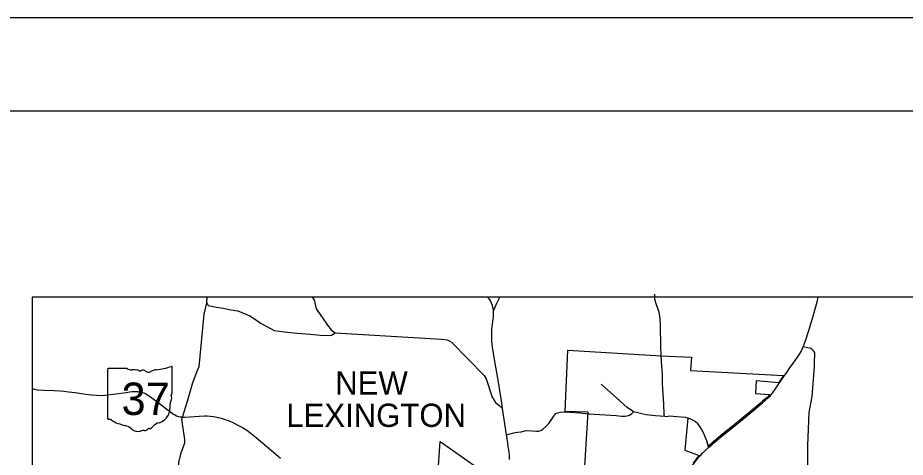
# Model space of a CAD drawing. Extents: x 2025369 to 2161369, y 549489 to 637489.
# Drawn here: x 2037061 to 2056140, y 628050 to 637489 of the extents above; entities that cross this region are included whole.
import ezdxf

# ---------------------------------------------------------------- set-up
doc = ezdxf.new("R2010")
doc.units = 0
for name, color, linetype in [('GM_X_City_Street', 7, 'Continuous'), ('GM_X_Corporation', 7, 'Continuous'), ('GM_X_Corporation_Text', 7, 'Continuous'), ('GM_X_County_Road', 7, 'Continuous'), ('GM_X_State_Route', 7, 'Continuous'), ('GM_X_State_Shield', 7, 'Continuous'), ('GM_X_Township_Road', 7, 'Continuous'), ('SH_Border', 7, 'Continuous'), ('SH_Cut_Line', 7, 'Continuous'), ('SH_Text', 7, 'Continuous')]:
    doc.layers.add(name, color=color, linetype=linetype)

msp = doc.modelspace()

# ---------------------------------------------------------------- linework, layer by layer
at = {"layer": 'GM_X_City_Street'}
for points in [[(2050948, 629193), (2050923, 629623), (2050918, 629823), (2050899, 630109), (2050894, 630227)], [(2050296, 629026), (2050165, 629116), (2049936, 629326), (2049604, 629618)], [(2051492, 628881), (2051465, 628890), (2051421, 628902), (2051231, 628921), (2051074, 628929), (2051012, 628921), (2050971, 628925), (2050962, 628938), (2050956, 628955), (2050956, 628979), (2050957, 629046), (2050953, 629116), (2050948, 629193)], [(2049328, 628983), (2049344, 628981), (2049928, 628947), (2050050, 628935), (2050113, 628934), (2050163, 628940), (2050209, 628953), (2050262, 628986), (2050296, 629026)], [(2050971, 628925), (2050768, 628940), (2050572, 628961), (2050507, 628972), (2050393, 629000), (2050296, 629026)]]:
    msp.add_lwpolyline(points, dxfattribs=at)
at = {"layer": 'GM_X_Corporation'}
for points in [[(2049232, 627516), (2049320, 629021), (2048826, 629034), (2048887, 630349), (2050894, 630227), (2051545, 630201), (2051523, 629916), (2053521, 629807), (2053413, 629647), (2052932, 629688), (2052923, 629416), (2053232, 629396), (2053172, 629333), (2053151, 629315), (2053074, 629251), (2052997, 629187), (2052901, 629107), (2052857, 629070), (2052770, 628998), (2052662, 628907), (2052454, 628735), (2052292, 628613), (2052177, 628518), (2052125, 628473), (2052018, 628381), (2051911, 628289), (2051871, 628405), (2051806, 628571), (2051763, 628653), (2051720, 628727), (2051679, 628770), (2051627, 628816), (2051570, 628846), (2051513, 628873), (2051465, 628890), (2051402, 628198), (2051709, 628087), (2051675, 628051), (2051584, 627925)], [(2045949, 625559), (2046139, 628388), (2047199, 627645)]]:
    msp.add_lwpolyline(points, dxfattribs=at)
at = {"layer": 'GM_X_County_Road'}
for points in [[(2043393, 631489), (2043434, 631429), (2043473, 631239), (2043610, 631045), (2043723, 630884), (2043800, 630784), (2043882, 630723), (2046170, 630587), (2046245, 630580), (2046289, 630568), (2046333, 630553), (2046385, 630524), (2047089, 629802), (2047129, 629735), (2047261, 629343), (2047299, 629285), (2047332, 629227), (2047410, 629158), (2047483, 629097)], [(2047287, 631186), (2047362, 631359), (2047426, 631489)], [(2040757, 627223), (2040694, 627429), (2040573, 627662), (2040530, 627804), (2040522, 627934), (2040573, 628142), (2040655, 628358), (2040656, 628420), (2040648, 628484), (2040627, 628626), (2040590, 628862), (2040600, 628913)], [(2047567, 628533), (2047649, 628555), (2047694, 628568), (2047751, 628582), (2047802, 628589), (2047881, 628594), (2047991, 628623), (2048123, 628614), (2048213, 628612), (2048256, 628612), (2048286, 628618), (2048320, 628632), (2048352, 628654), (2048416, 628710), (2048475, 628774), (2048543, 628867), (2048588, 628934), (2048628, 628986), (2048665, 629006), (2048718, 629021), (2048806, 629026), (2049148, 629001), (2049328, 628983)], [(2051907, 628256), (2051871, 628405), (2051806, 628571), (2051763, 628653), (2051720, 628727), (2051679, 628770), (2051627, 628816), (2051570, 628846), (2051513, 628873), (2051492, 628881)]]:
    msp.add_lwpolyline(points, dxfattribs=at)
at = {"layer": 'GM_X_State_Route'}
for points in [[(2047635, 628003), (2047629, 628085), (2047622, 628160), (2047616, 628206), (2047606, 628268), (2047594, 628360), (2047567, 628533), (2047483, 629097), (2047457, 629261), (2047371, 629790), (2047319, 630107), (2047270, 630411), (2047254, 630536), (2047252, 630577), (2047250, 630621), (2047250, 630662), (2047250, 630705), (2047252, 630745), (2047256, 630793), (2047283, 631023), (2047286, 631058), (2047289, 631105), (2047288, 631160), (2047287, 631186), (2047280, 631247), (2047265, 631311), (2047248, 631356), (2047222, 631412), (2047202, 631445), (2047177, 631482), (2047170, 631489)], [(2053927, 630370), (2053927, 630371), (2053947, 630418), (2053994, 630552), (2054064, 630770), (2054161, 631081), (2054244, 631385), (2054271, 631489)], [(2053544, 629802), (2053592, 629872), (2053660, 629970), (2053770, 630125), (2053823, 630199), (2053869, 630263), (2053902, 630320), (2053927, 630370)], [(2053425, 629628), (2053544, 629802)], [(2053240, 629372), (2053243, 629376), (2053268, 629404), (2053302, 629450), (2053349, 629516), (2053425, 629628)], [(2037369, 629532), (2037380, 629526), (2037421, 629513), (2037481, 629501), (2037616, 629492), (2037843, 629481), (2037965, 629474), (2038056, 629467), (2038155, 629456), (2038297, 629438), (2038429, 629419), (2038528, 629405), (2038648, 629389), (2038756, 629380), (2038849, 629377), (2038931, 629382), (2039170, 629411), (2039391, 629443), (2039472, 629454), (2039518, 629460), (2039570, 629463), (2039610, 629464), (2039649, 629462), (2039689, 629455), (2039721, 629449), (2039774, 629432), (2039816, 629413), (2039853, 629393), (2039918, 629350), (2040111, 629203), (2040236, 629106), (2040347, 629022), (2040411, 628976), (2040439, 628959), (2040476, 628941), (2040518, 628926), (2040552, 628918), (2040578, 628914), (2040600, 628913), (2040663, 628913), (2040959, 628931), (2041076, 628937), (2041136, 628936), (2041195, 628931), (2041270, 628922), (2041344, 628908), (2041431, 628888), (2041521, 628863), (2041609, 628832), (2041701, 628789), (2041795, 628741), (2041890, 628686), (2041984, 628628), (2042082, 628558), (2042184, 628474), (2042513, 628194), (2042660, 628071), (2042708, 628033)], [(2051907, 628256), (2051979, 628318), (2052028, 628359), (2052163, 628474), (2052312, 628594), (2052450, 628705), (2052516, 628758), (2052675, 628890), (2052890, 629067), (2053069, 629216), (2053193, 629324), (2053215, 629347), (2053240, 629372)], [(2051423, 627629), (2051427, 627643), (2051439, 627681), (2051451, 627705), (2051601, 627923), (2051657, 627999), (2051685, 628034), (2051713, 628066), (2051742, 628097), (2051785, 628144), (2051846, 628200), (2051907, 628256)]]:
    msp.add_lwpolyline(points, dxfattribs=at)
at = {"layer": 'GM_X_State_Shield'}
for p, q in [((2038991, 629939), (2038991, 628882)), ((2039413, 629957), (2039005, 629957)), ((2040384, 629431), (2040384, 629983)), ((2040383, 629431), (2040384, 629431))]:
    msp.add_line(p, q, dxfattribs=at)
for centre, radius, start, end in [((2039888, 631398), 1476, 275.8445, 288.9065), ((2040368, 629986), 15.5, 351.8621, 97.738), ((2039007, 629941), 16.1, 98.1301, 188.1301), ((2039510, 630080), 156, 231.6195, 271.1119), ((2039562, 629364), 562, 80.4867, 94.9883), ((2039689, 629947), 45.1, 219.7921, 297.1024), ((2039756, 629825), 93.8, 54.4667, 119.1411), ((2039877, 629992), 113, 233.8562, 294.8282), ((2040076, 629635), 297, 97.3462, 120.7689), ((2040367, 629429), 16.6, 289.6038, 7.7341), ((2040439, 629199), 105, 136.8065, 186.9296), ((2040380, 629390), 24, 107.944, 210.337), ((2040227, 629320), 144, 340.033, 23.6496), ((2039970, 629129), 369, 292.3089, 8.9858), ((2039008, 628880), 16.3, 171.9584, 258.3066), ((2039010, 628988), 124, 267.339, 280.6039), ((2039035, 628821), 44.8, 29.7484, 93.2717), ((2039601, 629771), 1066, 240.4129, 257.1985), ((2039283, 628408), 334, 47.1842, 75.836), ((2039644, 628816), 212, 230.7004, 286.2918), ((2039781, 628737), 113, 268.777, 315.5493), ((2039883, 628635), 31.8, 65.7517, 132.6484), ((2039870, 628780), 119, 282.8732, 323.2771), ((2040126, 628586), 202, 94.4031, 142.5768), ((2039766, 628451), 174, 85.6951, 111.2099)]:
    msp.add_arc(centre, radius, start, end, dxfattribs=at)
at = {"layer": 'GM_X_Township_Road'}
for points in [[(2050894, 630227), (2050883, 630444), (2050878, 630858), (2050870, 631034), (2050852, 631156), (2050823, 631243), (2050795, 631324), (2050758, 631440), (2050756, 631483), (2050755, 631552)], [(2040600, 628913), (2040707, 629252), (2040828, 629652), (2040931, 629932), (2040961, 630002), (2041020, 630593), (2041066, 631124), (2041124, 631363), (2041133, 631489)], [(2041124, 631363), (2041151, 631306), (2041334, 631271), (2041484, 631255), (2041642, 631218), (2041793, 631191), (2042050, 631090), (2042194, 630992), (2042295, 630921), (2042429, 630849), (2042574, 630772), (2042786, 630741), (2043071, 630714), (2043347, 630691), (2043566, 630672), (2043744, 630662), (2043806, 630675), (2043882, 630723)], [(2054015, 627099), (2054053, 627346), (2054067, 627456), (2054051, 627675), (2054048, 627879), (2054049, 628300), (2054059, 628653), (2054075, 629014), (2054139, 629355), (2054186, 630001), (2054188, 630084), (2054196, 630276), (2054194, 630295), (2054187, 630310), (2054167, 630338), (2054145, 630360), (2054109, 630382), (2054085, 630389), (2053947, 630418)]]:
    msp.add_lwpolyline(points, dxfattribs=at)
at = {"layer": 'SH_Border'}
msp.add_lwpolyline([(2033369, 635489), (2159369, 635489), (2159369, 551489), (2033369, 551489)], close=True, dxfattribs=at)
at = {"layer": 'SH_Cut_Line'}
msp.add_lwpolyline([(2025369, 549489), (2161369, 549489), (2161369, 637489), (2025369, 637489)], close=True, dxfattribs=at)
at = {"layer": 'SH_Text'}
msp.add_line((2092420, 631489), (2037369, 631489), dxfattribs=at)
msp.add_lwpolyline([(2037369, 631489), (2037369, 571561), (2092420, 571561), (2092420, 631489)], dxfattribs=at)

# ---------------------------------------------------------------- texts
at = {"layer": 'GM_X_Corporation_Text'}
for s, p in [('NEW', (2043886, 629393)), ('LEXINGTON', (2042834, 628701))]:
    msp.add_text(s, height=500, rotation=0, dxfattribs=at).set_placement(p)
at = {"layer": 'GM_X_State_Shield'}
msp.add_text('37', height=696.1, dxfattribs=at).set_placement((2039292, 628957))

doc.saveas('drawing.dxf')
